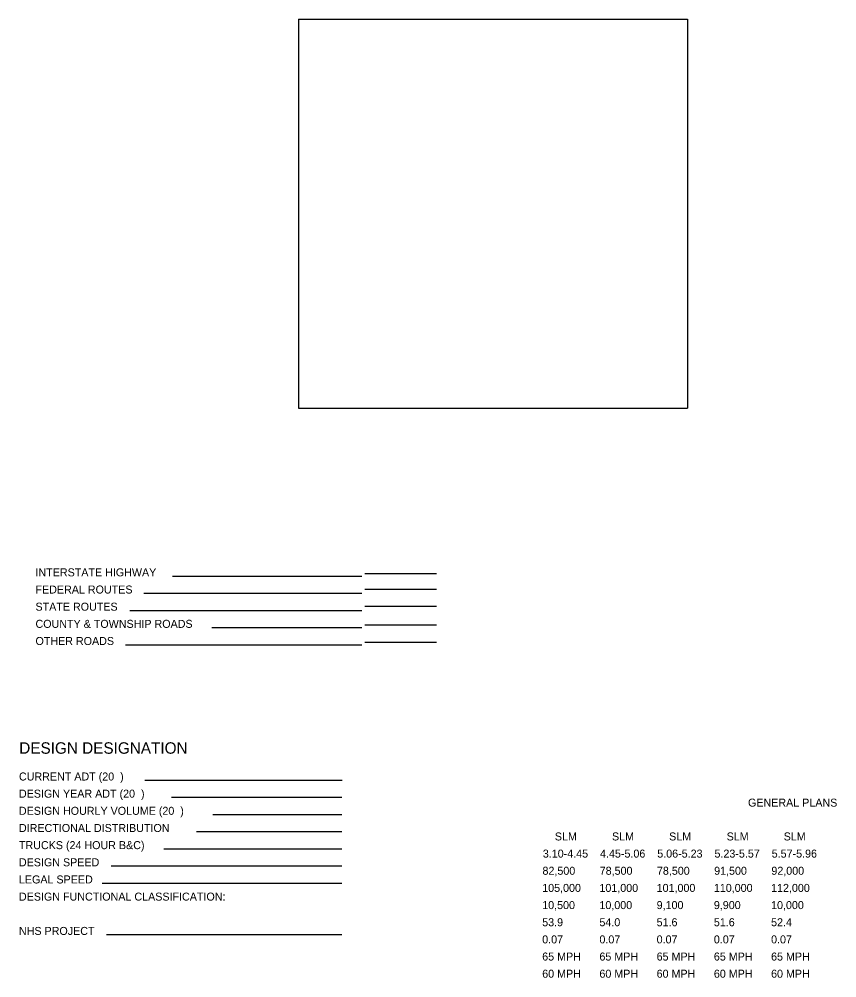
# Model space of a CAD drawing. Extents: x -17.5 to 72.9, y -57.8 to 32.3.
# Drawn here: x -17.48 to -3.19, y 8.13 to 24.89 of the extents above; entities that cross this region are included whole.
import ezdxf

# ---------------------------------------------------------------- set-up
doc = ezdxf.new("R2010")
doc.units = 0
doc.layers.add('SH_Data', color=7, linetype='Continuous')
doc.layers.add('SH_Text', color=7, linetype='Continuous')

msp = doc.modelspace()

# ---------------------------------------------------------------- linework, layer by layer
at = {"layer": 'SH_Data'}
for p, q in [((-12.599, 24.886), (-12.599, 18.086)), ((-12.599, 24.886), (-5.799, 24.886)), ((-5.799, 24.886), (-5.799, 18.086)), ((-12.599, 18.086), (-5.799, 18.086)), ((-11.49, 15.144), (-14.8, 15.144)), ((-10.19, 15.188), (-11.44, 15.188)), ((-11.49, 14.844), (-15.305, 14.844)), ((-10.19, 14.916), (-11.44, 14.916)), ((-10.19, 14.616), (-11.44, 14.616)), ((-11.49, 14.544), (-15.545, 14.544)), ((-10.19, 14.289), (-11.44, 14.289)), ((-11.49, 14.244), (-14.112, 14.244)), ((-11.49, 13.944), (-15.624, 13.944)), ((-10.19, 13.989), (-11.44, 13.989)), ((-11.837, 11.575), (-15.286, 11.575)), ((-11.843, 11.275), (-14.82, 11.275)), ((-11.843, 10.975), (-14.094, 10.975)), ((-11.843, 10.675), (-14.381, 10.675)), ((-11.843, 10.375), (-14.954, 10.375)), ((-11.843, 10.075), (-15.876, 10.075)), ((-11.843, 9.775), (-16.031, 9.775)), ((-11.843, 8.875), (-15.955, 8.875))]:
    msp.add_line(p, q, dxfattribs=at)

# ---------------------------------------------------------------- texts
for s, height, p in [('DESIGN DESIGNATION', 0.2, (-17.48, 12.043)), ('GENERAL PLANS', 0.14, (-4.743, 11.118)), ('SLM', 0.14, (-8.119, 10.527)), ('SLM', 0.14, (-7.12, 10.527)), ('SLM', 0.14, (-6.121, 10.527)), ('SLM', 0.14, (-5.117, 10.527)), ('SLM', 0.14, (-4.12, 10.527)), ('3.10-4.45', 0.14, (-8.329, 10.227)), ('4.45-5.06', 0.14, (-7.329, 10.227)), ('5.06-5.23', 0.14, (-6.329, 10.227)), ('5.23-5.57', 0.14, (-5.329, 10.227)), ('5.57-5.96', 0.14, (-4.329, 10.227)), ('82,500', 0.14, (-8.335, 9.927)), ('78,500', 0.14, (-7.335, 9.927)), ('78,500', 0.14, (-6.335, 9.927)), ('91,500', 0.14, (-5.335, 9.927)), ('92,000', 0.14, (-4.335, 9.927)), ('105,000', 0.14, (-8.34, 9.627)), ('101,000', 0.14, (-7.34, 9.627)), ('101,000', 0.14, (-6.34, 9.627)), ('110,000', 0.14, (-5.34, 9.627)), ('112,000', 0.14, (-4.34, 9.627)), ('10,500', 0.14, (-8.34, 9.327)), ('10,000', 0.14, (-7.34, 9.327)), ('9,100', 0.14, (-6.34, 9.327)), ('9,900', 0.14, (-5.34, 9.327)), ('10,000', 0.14, (-4.34, 9.327)), ('53.9', 0.14, (-8.34, 9.027)), ('54.0', 0.14, (-7.34, 9.027)), ('51.6', 0.14, (-6.34, 9.027)), ('51.6', 0.14, (-5.34, 9.027)), ('52.4', 0.14, (-4.34, 9.027)), ('0.07', 0.14, (-8.34, 8.727)), ('0.07', 0.14, (-7.34, 8.727)), ('0.07', 0.14, (-6.34, 8.727)), ('0.07', 0.14, (-5.34, 8.727)), ('0.07', 0.14, (-4.34, 8.727)), ('65 MPH', 0.14, (-8.34, 8.427)), ('65 MPH', 0.14, (-7.34, 8.427)), ('65 MPH', 0.14, (-6.34, 8.427)), ('65 MPH', 0.14, (-5.34, 8.427)), ('65 MPH', 0.14, (-4.34, 8.427)), ('60 MPH', 0.14, (-8.34, 8.127)), ('60 MPH', 0.14, (-7.34, 8.127)), ('60 MPH', 0.14, (-6.34, 8.127)), ('60 MPH', 0.14, (-5.34, 8.127)), ('60 MPH', 0.14, (-4.34, 8.127))]:
    msp.add_text(s, height=height, dxfattribs=at).set_placement(p)
at = {"layer": 'SH_Text'}
for s, p in [('INTERSTATE HIGHWAY', (-17.196, 15.144)), ('FEDERAL ROUTES', (-17.196, 14.844)), ('STATE ROUTES', (-17.196, 14.544)), ('COUNTY & TOWNSHIP ROADS', (-17.196, 14.244)), ('OTHER ROADS', (-17.196, 13.944)), ('CURRENT ADT (20  )', (-17.485, 11.575)), ('DESIGN YEAR ADT (20  )', (-17.485, 11.275)), ('DESIGN HOURLY VOLUME (20  )', (-17.485, 10.975)), ('DIRECTIONAL DISTRIBUTION', (-17.485, 10.675)), ('TRUCKS (24 HOUR B&C)', (-17.485, 10.375)), ('DESIGN SPEED', (-17.485, 10.075)), ('LEGAL SPEED', (-17.485, 9.775)), ('DESIGN FUNCTIONAL CLASSIFICATION:', (-17.485, 9.475)), ('NHS PROJECT', (-17.485, 8.875))]:
    msp.add_text(s, height=0.14, dxfattribs=at).set_placement(p)

doc.saveas('drawing.dxf')
